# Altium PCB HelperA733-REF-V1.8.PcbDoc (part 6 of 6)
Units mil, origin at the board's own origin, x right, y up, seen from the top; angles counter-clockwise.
Board outline 5905.51 x 4133.86 mil, 2 copper layers (Top, Bottom), stack 12.7 mil thick; 475 components, 355 nets, 1867 pads, 1471 vias.
Unrouted connection lines stored in the file: 1178.
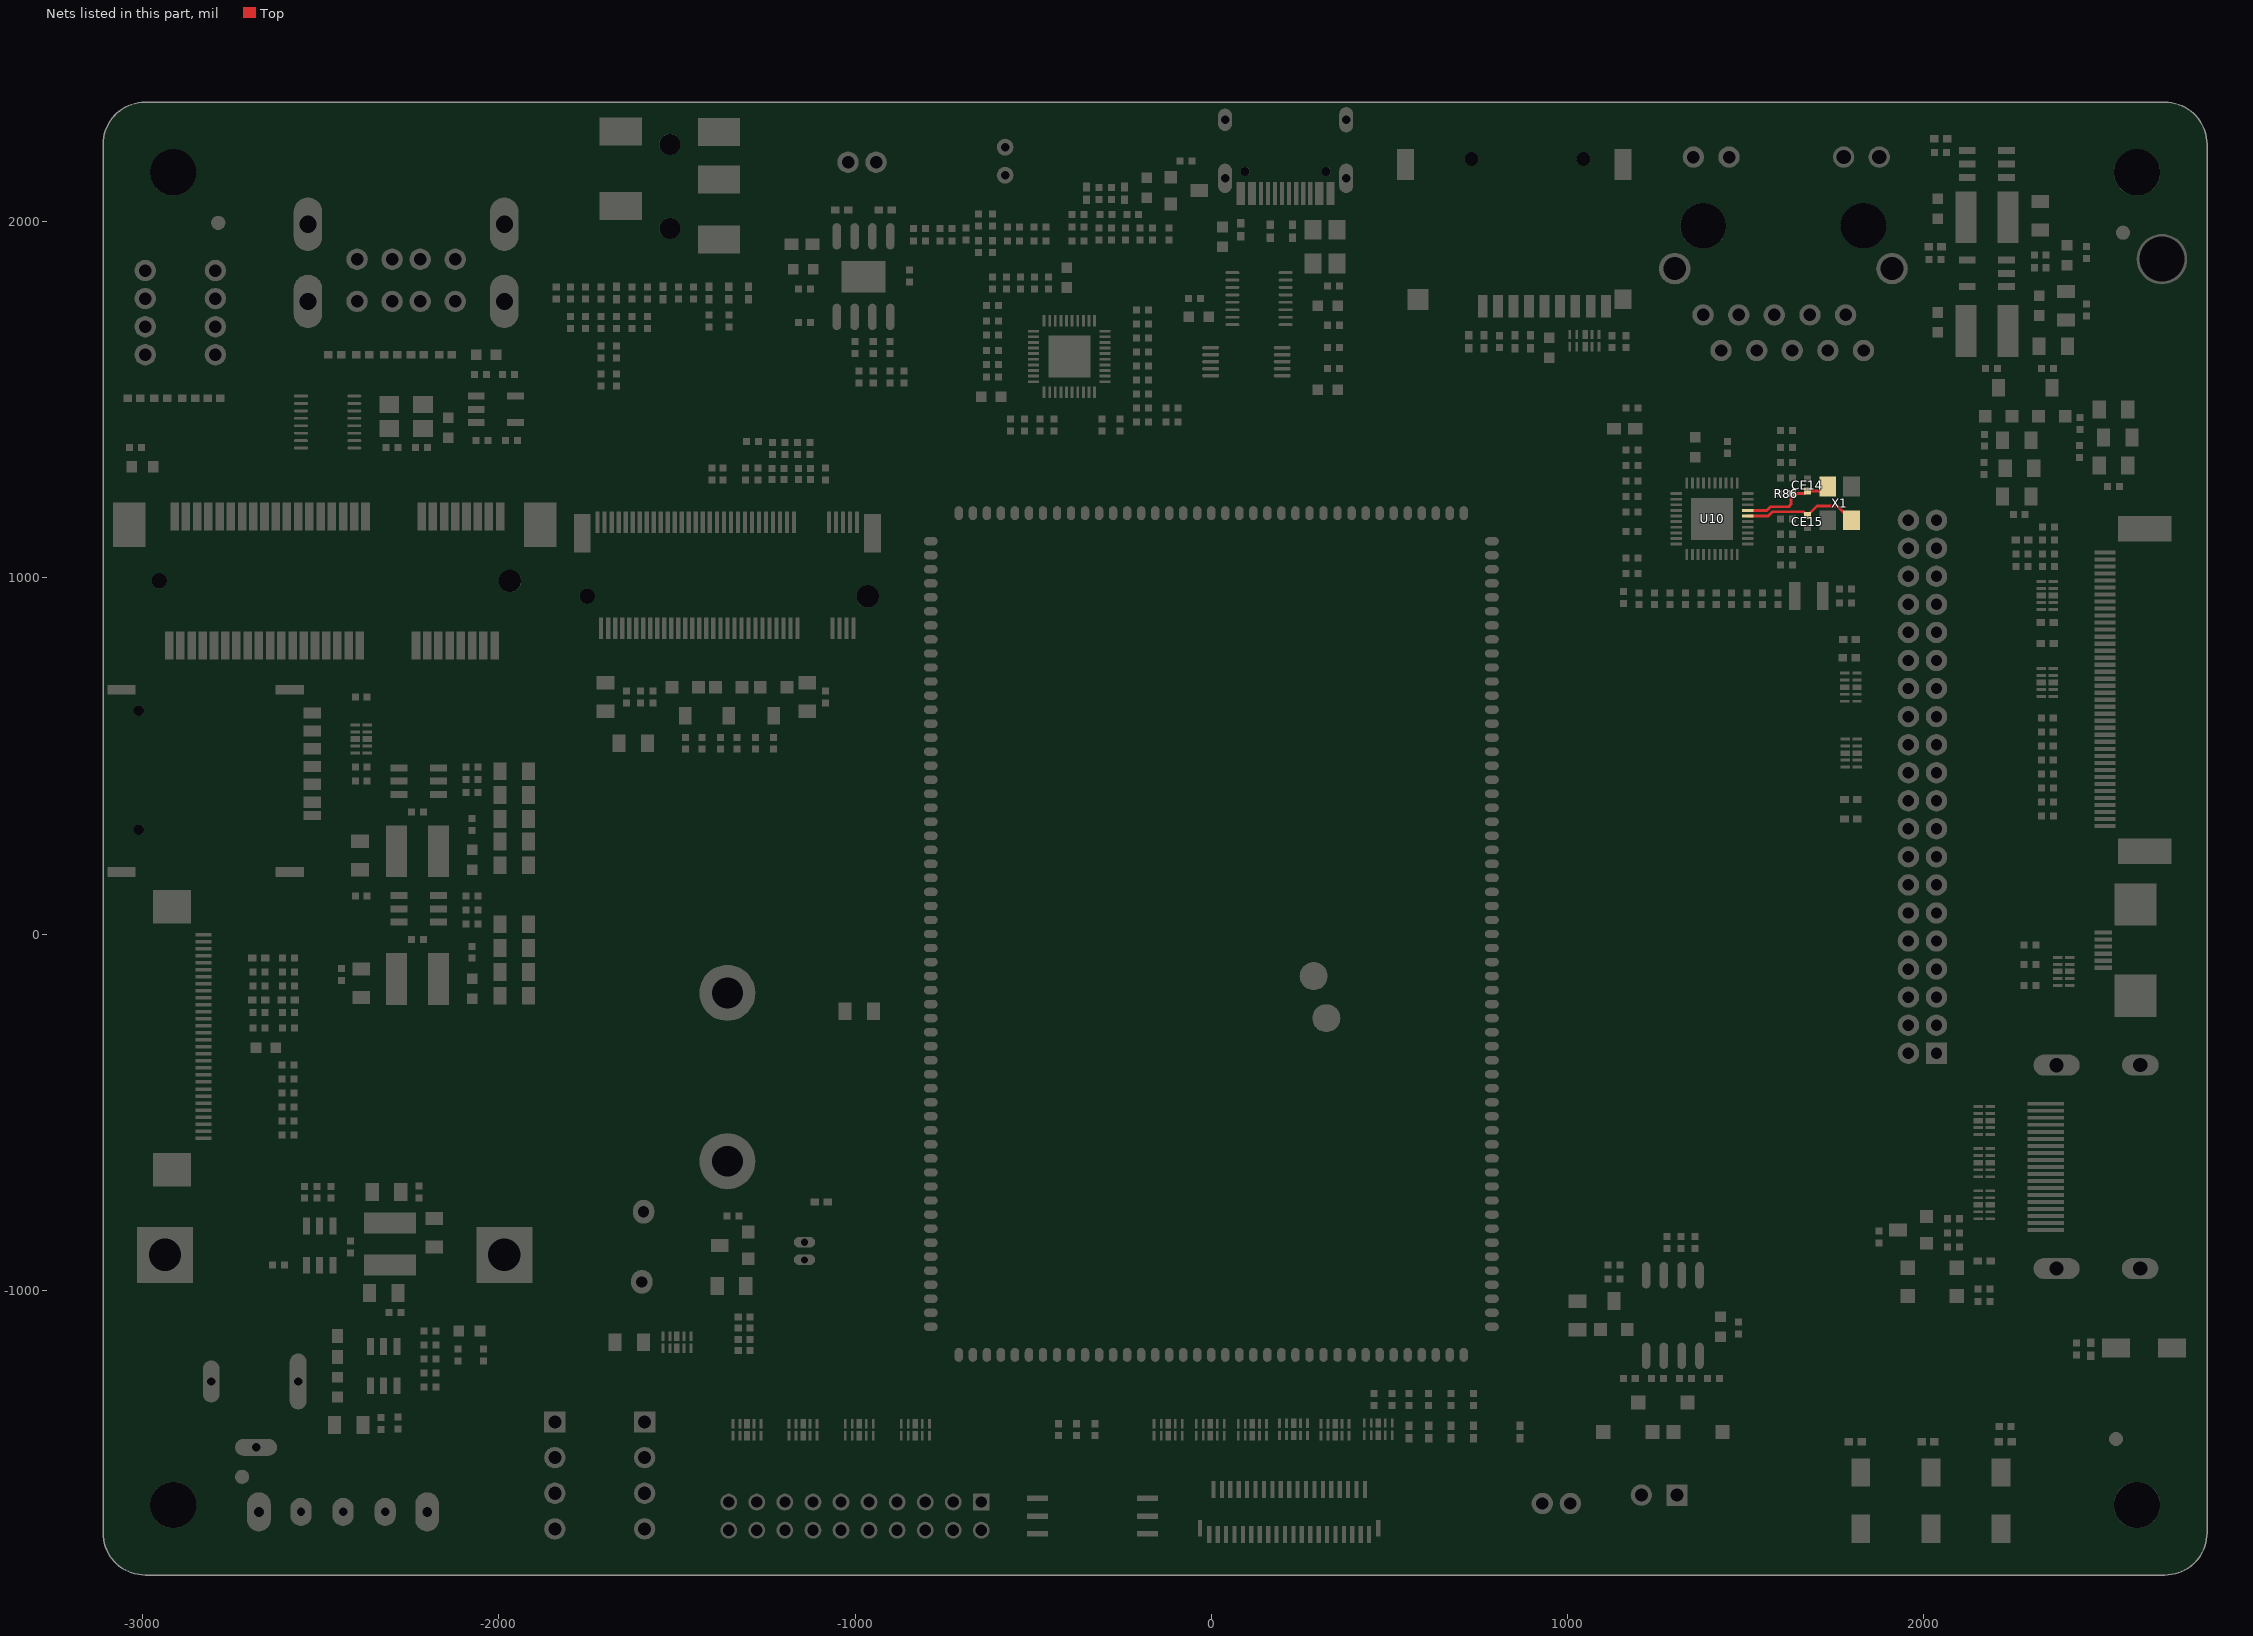
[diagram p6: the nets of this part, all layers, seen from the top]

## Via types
v1: diameter 22, hole 12, Top to Bottom, 1469 vias
v2: diameter 39.37, hole 35.43, Top to Bottom, 2 vias

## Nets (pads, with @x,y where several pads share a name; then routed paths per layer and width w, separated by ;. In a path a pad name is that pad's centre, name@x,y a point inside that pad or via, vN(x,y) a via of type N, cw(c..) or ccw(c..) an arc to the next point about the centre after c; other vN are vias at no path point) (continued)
XTAL-25MIN: CE15.2 U10.36 X1.3 | length 328.6
  Top w8: U10.36@1505.91,1173.23 1563.15,1173.23 1575.13,1185.21 1662.23,1185.21 CE15.2@1673.23,1174.21 1700.46,1201.45 1756.77,1201.45 1782.76,1175.46 X1.3@1797.24,1161.42
XTAL-25MOUT: CE14.2 R86.2 U10.37 X1.1 | length 266.9
  Top w8: U10.37@1505.91,1188.98 1559.1,1188.98 1569.35,1199.23 1620.57,1199.23 1627.38,1206.03 1627.38,1226.44 R86.2@1630.91,1236.22 1666.34,1236.22 CE14.2@1673.23,1243.11 1717.52,1243.11 X1.1@1730.32,1255.91
pads on no net: CON2.1 CON2.14 CON2.24 CON2.25 CON2.30 CON2.31 CON2.32 CON3.1 CON3.3 CON3.5 CON3.6 CON3.7 CON3.11 CON3.13 CON3.16 CON3.17 CON3.19 CON3.22 CON3.23 CON3.25 CON3.28 CON3.30 CON3.31 CON3.32 CON3.33 CON3.44 CON3.45 CON3.46 CON3.47 CON3.48 CON3.49 CON3.50 CON3.51 CON3._/2 CON3._/3 CON3.G1 CON3.G2 FID1.1 FID2.1 FID3.1 FID4.1 H1.1 H2.1 H3.1 H4.1 J2.1 J2.4 J2.5 J4.4 J4.23 J4.24 J4.26 J4.27 J4.36 J4.37 J4.41 J4.42 J5.7 J5.8 J7._ J7._/2 J11.1 J11.6 J11.7 J12.5 J12.6 J12.7 J12.8 J12.10 J12.11 J12.13 J12.17 J12.19 J12.20 J12.22 J12.23 J12.24 J12.25 J12.26 J12.28 J12.29 J12.30 J12.31 J12.32 J12.34 J12.35 J12.36 J12.37 J12.38 J12.40 J12.42 J12.44 J12.46 J12.48 J12.56 J12.58 J12.67 J12.68 J12.69 J12.78 J12.79 J12.MH1 J12.MH2 J18.15 J18.16 J18.17 J18.18 J19.17 J19.18 J19.A5 J19.A8 J19.B5 J19.B8 J21.4 J21.6 J21.12 J21.13 U1.1 U1.2 U1.5 U1.141 U1.142 U1.143 U1.144 U1.146 U1.151 U1.152 U1.153 U1.154 U1.159 U1.160 U1.161 U1.176 U10.34 U11.3 U11.4 U11.13 U11.14 U12.4 U12.5 U12.6 U14.14 U42.7 X2.2 X2.4 X3.2 X3.4
copper on no net: | length 0.1

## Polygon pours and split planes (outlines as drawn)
GND on Bottom (solid, remove dead copper, pour order 0): -3586.61,2645.67 -3586.61,-1929.13 3141.73,-1929.13 3141.73,2645.67
GND on Top (solid, remove dead copper, pour order 2): -3637.8,2732.28 -3637.8,-2003.94 3322.83,-2003.94 3322.83,2732.28

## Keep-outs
Top:
  region: 749.53,1598.38 749.53,1596.38 775.53,1596.38 775.53,1598.38 749.53,1598.38
  region: 1622.7,988.29 1622.7,908.89 1733.43,908.89 1733.43,988.29 1622.7,988.29
  region: 1264.42,1461.63 1264.42,1459.63 1286.42,1459.63 1286.42,1461.63 1264.42,1461.63
  region: 2136.42,-692.37 2136.42,-712.37 2138.42,-712.37 2138.42,-692.37 2136.42,-692.37
  region: 2080.02,1764.06 2080.02,1621.91 2263.97,1621.91 2263.97,1764.06 2080.02,1764.06
  region: -2378.45,-958.67 -2232.78,-958.67 -2232.78,-784.92 -2378.45,-784.92 -2378.45,-958.67
  region: -2315.81,304.68 -2315.81,159.93 -2145.15,159.93 -2145.15,304.68 -2315.81,304.68
  region: 912.42,-312.37 912.42,-338.37 914.42,-338.37 914.42,-312.37 912.42,-312.37
  region: 862.42,-428.37 862.42,-466.37 864.42,-466.37 864.42,-428.37 862.42,-428.37
  region: 261.64,1854.62 375.81,1854.62 375.81,2003.99 261.64,2003.99 261.64,1854.62
  region: 1706.29,1285.11 1706.29,1130.35 1823.74,1130.35 1823.74,1285.11 1706.29,1285.11
  region: 777.53,1580.38 777.53,1576.38 809.53,1576.38 809.53,1580.38 777.53,1580.38
  region: 316.42,-1620.37 316.42,-1622.37 332.42,-1622.37 332.42,-1620.37 316.42,-1620.37
  region: 1055.53,-1053.62 1055.53,-1055.62 1077.53,-1055.62 1077.53,-1053.62 1055.53,-1053.62
  region: 2090.55,2078.74 2090.55,1947.59 2264.3,1947.59 2264.3,2078.74 2090.55,2078.74
  region: 976.42,-404.37 976.42,-428.37 978.42,-428.37 978.42,-404.37 976.42,-404.37
  region: -2334.75,1509.97 -2334.75,1395.8 -2185.38,1395.8 -2185.38,1509.97 -2334.75,1509.97
  region: -2314.96,-53.01 -2314.96,-198.82 -2141.21,-198.82 -2141.21,-53.01 -2314.96,-53.01
Keep-Out Layer:
  lines w10: -1920.89,-1172.17 -1787.03,-1172.17 ; 100.44,-881.13 218.55,-881.13 ; 100.44,910.76 218.55,910.76 ; 1996.44,-1172.17 2130.3,-1172.17 ; -3110.65,-1681.1 ccw(c-2992.54,-1681.1) -2992.54,-1799.21 2676.76,-1799.21 ccw(c2676.76,-1681.1) 2794.87,-1681.1 2794.87,2216.54 ccw(c2676.76,2216.54) 2676.76,2334.65 -2992.54,2334.65 ccw(c-2992.54,2216.54) -3110.65,2216.54 -3110.65,-1681.1

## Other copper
Top:
  region net N5679088: -2472.44,-895.67 -2472.44,-952.76 -2462.6,-962.6 -2251.97,-962.6 -2251.97,-905.51 -2377.95,-905.51 -2395.67,-887.8 -2464.57,-887.8 -2472.44,-895.67
  region net REGOUT: 1475.19,1083.4 1471.19,1079.4 1471.19,1007.4 1487.19,991.4 1595.19,991.4 1611.19,975.4 1611.19,911.4 1615.19,907.4 1647.19,907.4 1651.19,911.4 1651.19,1011.4 1643.19,1019.4 1513.19,1019.4 1503.19,1029.4 1503.19,1079.4 1499.19,1083.4 1475.19,1083.4
  region net 12V-IN: -2629.92,-1174.46 -2629.92,-1350.39 -2576.77,-1403.54 -2429.13,-1403.54 -2418.31,-1392.72 -2418.31,-1354.33 -2401.23,-1337.26 -2360.82,-1337.26 -2343.14,-1354.95 -2341.2,-1353.01 -2321.45,-1353.01 -2321.45,-1332.09 -2344.49,-1309.06 -2344.49,-1240.16 -2409.45,-1240.16 -2419.29,-1250 -2419.29,-1275.59 -2424.21,-1280.51 -2472.44,-1280.51 -2490.65,-1262.3 -2490.65,-1188.98 -2505.17,-1174.46 -2629.92,-1174.46
  region net N17914691: 2142.72,1468.5 2142.72,1393.7 2146.65,1389.76 2193.9,1389.76 2197.83,1385.83 2197.83,1362.2 2201.77,1358.27 2237.2,1358.27 2241.14,1362.2 2241.14,1417.32 2237.2,1421.26 2205.71,1421.26 2201.77,1425.2 2201.77,1468.5 2197.83,1472.44 2146.65,1472.44 2142.72,1468.5
  region net PCIE-3V3: -1710.63,685.04 -1543.31,685.04 -1539.37,688.98 -1539.37,811.02 -1543.31,814.96 -1716.54,814.96 -1722.44,809.06 -1722.44,696.85 -1710.63,685.04
  region net N17914651: 2208.66,1822.83 2208.66,1712.6 2267.72,1712.6 2267.72,1822.83 2208.66,1822.83
  region net PCIE-3V3: -1147.64,688.98 -1070.87,688.98 -1070.87,720.47 -1035.43,755.91 -992.13,755.91 -992.13,818.9 -1122.05,818.9 -1147.64,793.31 -1147.64,688.98
  region net DCIN: -2515.75,-925.2 -2515.75,-960.63 -2539.37,-984.25 -2539.37,-1000 -2468.5,-1000 -2468.5,-984.25 -2488.19,-964.57 -2488.19,-925.2 -2515.75,-925.2
  region net VGH: 2422.24,1421.26 2422.24,1362.2 2426.18,1358.27 2469.49,1358.27 2473.42,1354.33 2473.42,1248.03 2477.36,1244.09 2524.61,1244.09 2528.54,1248.03 2528.54,1421.26 2524.61,1425.2 2426.18,1425.2 2422.24,1421.26
  region net 5V: -1641.73,-409.45 -1641.73,-468.5 -1578.74,-468.5 -1578.74,-409.45 -1641.73,-409.45
  region net DCIN: -2380.56,419.51 -2381.06,419.51 -2381.06,399.29 -2452.65,327.7 -2452.65,262.95 -2435.8,246.1 -2343.87,246.1 -2343.87,377.83 -2319.79,401.92 -2319.79,402.2 -2302.98,419.02 -2259.42,419.02 -2259.42,439.95 -2306.19,439.95 -2314.24,447.99 -2375.37,447.99 -2380.56,442.8 -2380.56,419.51
  region net N17914651: 2200.79,1610.24 2200.79,1578.74 2334.65,1578.74 2334.65,1669.29 2208.66,1669.29 2208.66,1610.24 2200.79,1610.24
  region net N17177143: -2305.12,43.31 -2305.12,-11.81 -2338.58,-45.28 -2338.58,-196.85 -2259.84,-196.85 -2259.84,-59.06 -2232.28,-31.5 -2232.28,23.62 -2251.97,43.31 -2305.12,43.31
  region net N17914681: 2351.38,1598.43 2351.38,1570.87 2339.57,1559.06 2339.57,1511.81 2343.5,1507.87 2398.62,1507.87 2402.56,1511.81 2402.56,1598.43 2398.62,1602.36 2355.31,1602.36 2351.38,1598.43
  region net N17914762: 2375.19,1467.4 2375.19,1440.72 2379.53,1436.38 2507.53,1436.38 2515.19,1444.04 2515.19,1495.4 2511.19,1499.4 2475.19,1499.4 2471.19,1495.4 2471.19,1475.4 2467.19,1471.4 2379.19,1471.4 2375.19,1467.4
  region net AVDD: 2359.25,1625.98 2363.19,1622.05 2469.49,1622.05 2473.42,1625.98 2473.42,1673.23 2469.49,1677.17 2434.05,1677.17 2430.12,1681.1 2430.12,1688.98 2434.05,1692.91 2469.49,1692.91 2473.42,1696.85 2473.42,1748.03 2296.26,1748.03 2292.32,1744.09 2292.32,1692.91 2296.26,1688.98 2355.31,1688.98 2359.25,1685.04 2359.25,1625.98
  region net AVDD33: 1319.19,1231.4 1323.19,1235.4 1323.19,1267.4 1319.19,1271.4 1272.5,1271.4 1239.53,1304.38 1239.53,1436.38 1236.5,1439.4 1167.19,1439.4 1163.19,1435.4 1163.19,1395.4 1187.67,1370.92 1187.67,1261.67 1189.95,1259.4 1199.19,1259.4 1227.19,1231.4 1319.19,1231.4
  region net 5V: 2023.62,2133.86 2023.62,2051.18 2145.67,2051.18 2145.67,2133.86 2023.62,2133.86
  region net PCIE-3V3: -2067.23,134.91 -2067.23,55.17 -2039.72,55.17 -2033.54,48.98 -2033.54,-38.48 -2056.3,-61.24 -2190.93,-61.24 -2190.93,-189.48 -2113.61,-189.48 -2113.61,-143.1 -2112.24,-141.73 -2042.74,-141.73 -2040.23,-144.24 -2040.23,-192.52 -2029.78,-202.97 -1959.25,-202.97 -1959.25,128.74 -1965.42,134.91 -2067.23,134.91
  region net N16925291: 2212.6,2133.86 2212.6,2039.37 2346.46,2039.37 2346.46,2133.86 2212.6,2133.86
  region net DCIN: -2353.86,328.77 -2450.73,328.77 -2486.48,293.02 -2513.39,293.02 -2529.12,277.3 -2529.12,142.15 -2536.55,134.72 -2755.07,134.72 -2772.56,117.23 -2772.56,6.22 -2767.35,1.01 -2783.94,-15.58 -2921.87,-15.58 -2925.3,-19.02 -2925.3,-85.62 -2726.52,-86.11 -2721.93,-84.21 -2720.02,-79.62 -2720.52,-79.62 -2720.52,-50.15 -2698.23,-27.86 -2517.98,-27.86 -2439.54,-106.3 -2356.67,-106.3 -2356.67,-49.14 -2314.84,-7.31 -2314.84,47.62 -2302.45,60.01 -2260.41,60.01 -2260.41,81.72 -2301.15,81.72 -2306.09,82.68 -2436.62,82.68 -2442.62,88.67 -2442.62,220.05 -2421.18,241.48 -2353.86,241.48 -2353.86,328.77
  region net PCIE-3V3: -2043.31,55.12 -1968.5,55.12 -1952.76,70.87 -1759.84,70.87 -1736.22,94.49 -1736.22,657.48 -1697.83,695.87 -1697.83,795.28 -1775.59,795.28 -1807.09,763.78 -1807.09,149.61 -1822.83,133.86 -2043.31,133.86 -2043.31,55.12
  region net N179147341: 2142.72,1598.43 2142.72,1511.81 2146.65,1507.87 2229.33,1507.87 2233.27,1511.81 2233.27,1555.12 2229.33,1559.06 2189.96,1559.06 2186.02,1562.99 2186.02,1598.43 2182.09,1602.36 2146.65,1602.36 2142.72,1598.43
  region net PCIE-3V3: -2128.73,-1021.29 -2128.73,-1045.29 -2056.73,-1045.29 -2056.73,-1021.29 -2128.73,-1021.29
  region net VGL: 2142.72,1377.95 2142.72,1314.96 2146.65,1311.02 2189.96,1311.02 2193.9,1307.09 2193.9,1177.17 2197.83,1173.23 2245.08,1173.23 2249.02,1177.17 2249.02,1342.52 2245.08,1346.46 2189.96,1346.46 2186.02,1350.39 2186.02,1377.95 2182.09,1381.89 2146.65,1381.89 2142.72,1377.95
  region net GND: 221.04,-54.04 221.04,-299.41 380.59,-299.41 380.59,-54.04 221.04,-54.04
  region net 5V: -2334.65,-795.28 -2334.65,-838.58 -2153.54,-838.58 -2153.54,-736.22 -2157.48,-732.28 -2295.28,-732.28 -2295.28,-755.91 -2334.65,-795.28
  region net DCIN: -2549.18,-980.32 -2549.18,-1049.18 -2515.75,-1082.62 -2421.2,-1082.62 -2409.33,-1094.49 -2409.33,-1173.11 -2397.64,-1184.79 -2346.7,-1184.79 -2343.01,-1181.1 -2343.01,-1125.49 -2308.07,-1090.55 -2308.07,-1044.29 -2320.87,-1031.5 -2320.87,-994.09 -2334.65,-980.32 -2549.18,-980.32
  region net N18148334: -2307.49,398.48 -2329.36,376.61 -2329.36,161.44 -2260.16,161.44 -2260.16,306.7 -2238.6,328.25 -2238.6,381.04 -2256.04,398.48 -2307.49,398.48
  region net DCIN: -2925.2,-11.81 -2925.2,-83.91 -2915.94,-93.16 -2868.7,-93.16 -2858.27,-82.73 -2858.27,-11.81 -2862.2,-7.87 -2921.26,-7.87 -2925.2,-11.81
  region net 5V: -1003.94,-195.43 -1007.87,-191.5 -1078.74,-191.5 -1082.68,-195.43 -1082.68,-369.98 -1066.83,-385.83 -1019.78,-385.83 -1003.94,-369.98 -1003.94,-195.43
  region net VCC_4G: -2062.61,486.44 -2062.61,429.32 -2051.81,418.52 -2041.98,418.52 -2038.05,414.59 -2038.05,318.19 -2057.74,298.5 -2169.04,298.5 -2169.04,160.13 -2125.98,160.13 -2125.98,210.03 -2123.41,212.6 -2022.63,212.6 -2019.68,209.66 -2019.68,170.79 -2015.39,166.49 -1961.64,166.49 -1961.64,491.34 -2057.72,491.34 -2062.61,486.44
  region net 5V: 2027.56,1842.52 2027.56,1728.35 2145.67,1728.35 2145.67,1842.52 2027.56,1842.52
Bottom:
  region net AVDD33: 1250.3,1429.64 1246.3,1433.64 1186.3,1433.64 1182.3,1429.64 1182.3,1317.64 1186.3,1313.64 1246.3,1313.64 1250.3,1317.64 1250.3,1429.64
  region net PCIE-3V3: -2128.73,-77.29 -2128.73,-129.29 -2100.73,-129.29 -2100.73,-77.29 -2128.73,-77.29
  region net PCIE-3V3: -1702.39,779.53 -1702.39,687.38 -1685.04,670.03 -1185.78,670.03 -1182.58,673.23 -1121.06,673.23 -1051.18,743.11 -999.02,743.11 -994.09,748.03 -994.09,785.43 -1000,791.34 -1173.23,791.34 -1236.22,728.35 -1496.06,728.35 -1547.24,779.53 -1702.39,779.53
  region net 5V: -1641.73,-405.51 -1641.73,-476.38 -1232.28,-476.38 -1155.51,-399.61 -1003.94,-399.61 -1003.94,-326.77 -1216.54,-326.77 -1295.28,-405.51 -1641.73,-405.51

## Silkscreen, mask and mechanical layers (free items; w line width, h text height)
Silkscreen Top:
  lines w5: -830.71,-157.48 -854.92,-157.48 -854.92,-118.11 -830.71,-118.11
  text "MIC" at -348.47,2152.38 h30
  text "+" at -1051.18,2059.06 h25
  text "SPK" at -1011.81,2055.12 h25
  text "-" at -929.13,2055.12 h25
  text "Phone Jack" at -1791.34,2027.56 h30 r90
  text "USB1" at -3051.18,1948.82 h30
  text "USB2" at -2755.91,1948.82 h30
  text "OTG" at 98.43,1885.83 h30
  text "G" at -2657.48,1850.39 h30
  text "DP" at -2657.48,1771.65 h30
  text "DM" at -2657.48,1692.91 h30
  text "TF" at 610.24,1641.73 h30
  text "5V" at -2657.48,1614.17 h30
  text "USB3/USB4" at -2417.32,1547.24 h30
  text "ETH 1000M" at 1456.69,1496.06 h30
  text "4G" at -2913.39,1299.21 h30
  text "M.2" at -1633.86,1259.84 h30
  text "20260415" at 1589.53,246.38 h39.37 r90
  text "LCD" at 2417.32,192.91 h30 r90
  text "SIM" at -2437.01,177.17 h30 r90
  text "百杰科技" at 1389.53,96.38 h98.43 r90
  text "CTP" at 2417.32,15.75 h30 r90
  text "HelperBoard A733 V1.8" at 1499.53,-73.62 h43.3 r90
  text "5V" at -917.32,-157.48 h30
  text "EDP" at -2657.48,-492.13 h30 r90
  text "LCD" at 1850.39,-511.81 h30 r90
  text "HDMI" at 2271.65,-692.91 h30 r90
  text "+" at -1204.72,-822.83 h30 r90
  text "RTC" at -1204.72,-925.2 h30 r90
  text "-" at -1208.66,-968.5 h30 r90
  text "DCIN_12V" at -2779.53,-1066.93 h30
  text "RESET" at 2551.18,-1287.4 h30
  text "UART4" at -2114.17,-1314.96 h30
  text "UART3" at -1433.07,-1314.96 h30
  text "3.3V" at -2070.87,-1393.7 h30
  text "ON/OFF" at -2500,-1476.38 h30
  text "TX" at -2066.93,-1496.06 h30
  text "CAMERA" at 150.58,-1499.84 h30
  text "KEY" at 850.39,-1511.81 h30
  text "3V3" at -771.65,-1519.69 h30
  text "5V" at -657.48,-1519.69 h30
  text "RX" at -2066.93,-1590.55 h30
  text "GND" at -2070.87,-1688.98 h30
  text "GND" at 858.27,-1763.78 h30
  text "LRADC" at 968.5,-1763.78 h30
  text "+" at 1181.1,-1763.78 h30
  text "485" at 1220.47,-1763.78 h30
  text "-" at 1318.9,-1763.78 h30
  text "LCD-SEL" at -433.07,-1771.65 h30
  text "FEL" at 1795.28,-1775.59 h30
  text "RST" at 1984.25,-1775.59 h30
  text "PWR" at 2173.23,-1775.59 h30
  text "G" at -732.28,-1779.53 h30
  text "G" at -653.54,-1779.53 h30
Assembly Drawing Top:
  circle w5: c-1932.54,1297.24 r2.5
  circle w5: c-1942.54,1298.3 r2.5
  circle w5: c1887.46,-524.54 r2.5
  circle w5: c2072.74,-453.87 r2.5
  circle w5: c-1942.54,1062.08 r2.5
  circle w5: c2072.74,1278.18 r2.5
  circle w5: c1914.59,-453.87 r2.5
  circle w5: c-1932.54,1297.24 r2.5
  circle w5: c-1434.67,-1024.54 r2.5
  circle w5: c-1942.54,1298.3 r2.5
  circle w5: c2107.46,-524.54 r2.5
  circle w5: c2107.46,1349.48 r2.5
  circle w5: c-1434.67,-1024.54 r2.5
  circle w5: c-1942.54,-1260.76 r2.5
  circle w5: c2151.95,-1260.76 r2.5
  circle w5: c2151.95,-1260.76 r2.5
  circle w5: c2151.95,1298.3 r2.5
  circle w5: c1914.59,-453.87 r2.5
  circle w5: c1887.46,1349.48 r2.5
  circle w5: c-1942.54,-1024.54 r2.5
  circle w5: c1914.59,1278.18 r2.5
  circle w5: c2072.74,-453.87 r2.5
  circle w5: c-1942.54,-1024.54 r2.5
  circle w5: c2151.46,1175.24 r2.5
  circle w5: c2107.46,1349.48 r2.5
  circle w5: c1914.59,1278.18 r2.5
  circle w5: c-1434.67,1062.08 r2.5
  circle w5: c-1942.54,-1260.76 r2.5
  circle w5: c2107.46,-524.54 r2.5
  circle w5: c2072.74,1278.18 r2.5
  circle w5: c1887.46,-524.54 r2.5
  circle w5: c-1434.67,1062.08 r2.5
  circle w5: c2151.46,1175.24 r2.5
  circle w5: c2151.95,1298.3 r2.5
  circle w5: c-1942.54,1062.08 r2.5
  circle w5: c1887.46,1349.48 r2.5
  lines w1: -3110.65,267.72 -3110.62,267.72 ; -157.89,2334.65 -157.86,2334.65 ; 2794.87,267.72 2794.89,267.72 ; 303.15,-1799.21 303.18,-1799.21
  lines w10: -3450.68,-1799.21 253.15,-1799.21 ; -3450.68,2334.65 -207.89,2334.65 ; -3400.68,153.69 -3400.68,-1799.21 ; -3400.68,559.14 -3400.68,2334.65 ; -3295.79,-1602.36 -2963.8,-1602.36 ; -3295.79,2137.8 -2963.8,2137.8 ; -3245.79,183.32 -3245.79,-1602.36 ; -3245.79,554.68 -3245.79,2137.8 ; -3110.65,317.72 -3110.65,2661.35 ; -2913.8,2187.8 -2913.8,2467.32 ; -360.62,2417.32 -2913.8,2417.32 ; -360.62,2611.35 -3110.65,2611.35 ; 44.84,2417.32 2598.02,2417.32 ; 44.84,2611.35 2794.87,2611.35 ; 2598.02,2187.8 2598.02,2467.32 ; 2794.87,317.72 2794.87,2661.35 ; -3400.68,-1799.21 -3375.68,-1699.21 -3425.68,-1699.21 -3400.68,-1799.21 ; -3400.68,2334.65 -3425.68,2234.65 -3375.68,2234.65 -3400.68,2334.65 ; -3245.79,-1602.36 -3220.79,-1502.36 -3270.79,-1502.36 -3245.79,-1602.36 ; -3245.79,2137.8 -3270.79,2037.8 -3220.79,2037.8 -3245.79,2137.8 ; -3110.65,2611.35 -3010.65,2586.35 -3010.65,2636.35 -3110.65,2611.35 ; -2913.8,2417.32 -2813.8,2392.32 -2813.8,2442.32 -2913.8,2417.32 ; 2598.02,2417.32 2498.02,2442.32 2498.02,2392.32 2598.02,2417.32 ; 2794.87,2611.35 2694.87,2636.35 2694.87,2586.35 2794.87,2611.35 ; -1942.54,-1260.76 -1942.54,-1024.54 -1434.67,-1024.54 -1434.67,1062.08 -1942.54,1062.08 -1942.54,1298.3 2151.95,1298.3 2151.95,-1260.76 -1942.54,-1260.76 ; -1936.63,-1172.17 cw(c-1853.96,-1172.17) -1771.28,-1172.17 cw(c-1853.96,-1172.17) -1936.63,-1172.17 ; -1936.63,1209.72 cw(c-1853.96,1209.72) -1771.28,1209.72 cw(c-1853.96,1209.72) -1936.63,1209.72 ; 1887.46,-524.54 1887.46,1349.48 2107.46,1349.48 2107.46,-524.54 1887.46,-524.54 ; 1914.59,-453.87 2072.74,-453.87 2072.74,1278.18 1914.59,1278.18 1914.59,-453.87 ; 1980.69,-1172.17 cw(c2063.37,-1172.17) 2146.04,-1172.17 cw(c2063.37,-1172.17) 1980.69,-1172.17
  text "150.0mm" at -330.62,2573.85 h50
  text "140.0mm" at -330.62,2379.82 h50
  text "95.0mm" at -3225.84,213.32 h50 r90
  text "105.0mm" at -3377.56,183.69 h50 r90
Assembly Drawing Bottom:
  circle w10: c-1853.15,1222.05 r68.76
